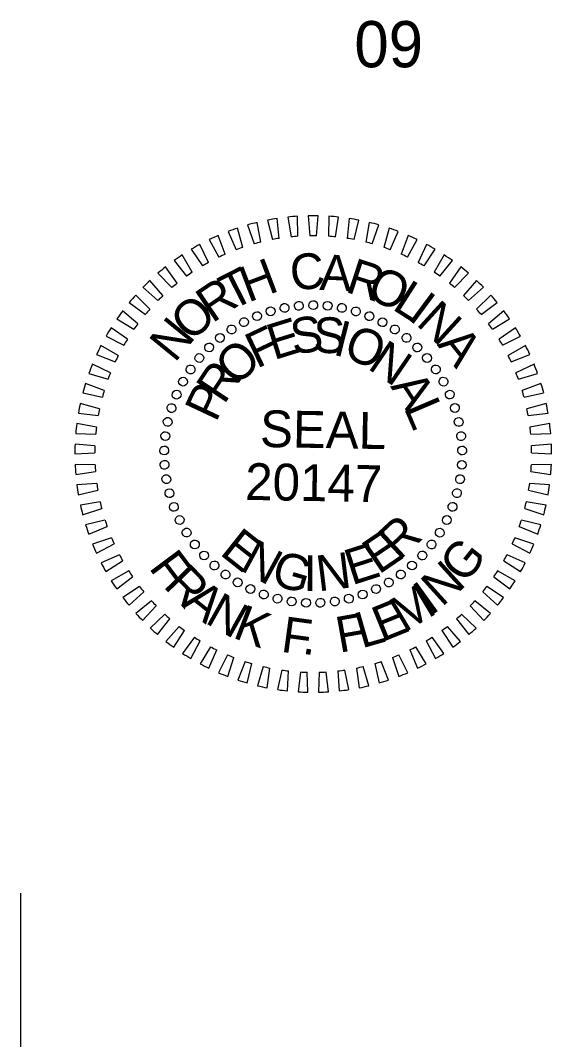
# Model space of a CAD drawing. Extents: x 2044664 to 2046614, y 755540 to 756566.
# Drawn here: x 2046401.6 to 2046490.8, y 756394.8 to 756565.9 of the extents above; entities that cross this region are included whole.
import ezdxf

# ---------------------------------------------------------------- set-up
doc = ezdxf.new("R2010")
doc.units = 0
for name, color, linetype in [('Matchline', 7, 'Continuous'), ('Sheet Data Field CELL', 7, 'Continuous'), ('Sheet PE Seal Cell', 7, 'Continuous')]:
    doc.layers.add(name, color=color, linetype=linetype)

msp = doc.modelspace()

# ---------------------------------------------------------------- linework, layer by layer
at = {"layer": 'Matchline'}
msp.add_line((2046401.63, 756419.36), (2046401.63, 756155.41), dxfattribs=at)
at = {"layer": 'Sheet PE Seal Cell'}
for p, q in [((2046443.1, 756532.35), (2046443.92, 756529.09)), ((2046445.05, 756529.29), (2046444.73, 756532.63)), ((2046446.51, 756532.86), (2046447.04, 756529.55)), ((2046448.19, 756529.65), (2046448.15, 756533)), ((2046449.94, 756533.08), (2046450.19, 756529.73)), ((2046451.34, 756529.73), (2046451.59, 756533.08)), ((2046453.38, 756533), (2046453.34, 756529.65)), ((2046454.49, 756529.55), (2046455.02, 756532.86)), ((2046456.8, 756532.63), (2046456.48, 756529.29)), ((2046457.61, 756529.09), (2046458.43, 756532.35)), ((2046436.49, 756530.45), (2046437.86, 756527.39)), ((2046438.94, 756527.78), (2046438.04, 756531.01)), ((2046439.76, 756531.54), (2046440.85, 756528.37)), ((2046441.96, 756528.67), (2046441.35, 756531.96)), ((2046460.18, 756531.96), (2046459.57, 756528.67)), ((2046460.68, 756528.37), (2046461.77, 756531.54)), ((2046463.49, 756531.01), (2046462.59, 756527.78)), ((2046463.68, 756527.39), (2046465.04, 756530.45)), ((2046433.33, 756529.09), (2046434.95, 756526.15)), ((2046436, 756526.63), (2046434.83, 756529.78)), ((2046466.7, 756529.78), (2046465.53, 756526.63)), ((2046466.58, 756526.15), (2046468.2, 756529.09)), ((2046430.3, 756527.46), (2046432.17, 756524.67)), ((2046433.17, 756525.24), (2046431.74, 756528.27)), ((2046469.79, 756528.27), (2046468.36, 756525.24)), ((2046469.36, 756524.67), (2046471.23, 756527.46)), ((2046427.42, 756525.57), (2046429.52, 756522.96)), ((2046430.47, 756523.61), (2046428.78, 756526.51)), ((2046472.75, 756526.51), (2046471.06, 756523.61)), ((2046472.01, 756522.96), (2046474.11, 756525.57)), ((2046427.92, 756521.75), (2046425.99, 756524.49)), ((2046475.54, 756524.49), (2046473.61, 756521.75)), ((2046425.54, 756519.68), (2046423.38, 756522.25)), ((2046424.72, 756523.44), (2046427.04, 756521.02)), ((2046474.49, 756521.02), (2046476.81, 756523.44)), ((2046478.15, 756522.25), (2046475.99, 756519.68)), ((2046422.2, 756521.09), (2046424.72, 756518.88)), ((2046476.81, 756518.88), (2046479.33, 756521.09)), ((2046419.9, 756518.53), (2046422.6, 756516.54)), ((2046423.35, 756517.41), (2046420.98, 756519.78)), ((2046480.55, 756519.78), (2046478.18, 756517.41)), ((2046478.93, 756516.54), (2046481.63, 756518.53)), ((2046421.36, 756514.97), (2046418.79, 756517.12)), ((2046482.74, 756517.12), (2046480.17, 756514.97)), ((2046417.83, 756515.79), (2046420.69, 756514.03)), ((2046480.84, 756514.03), (2046483.7, 756515.79)), ((2046419.59, 756512.36), (2046416.84, 756514.29)), ((2046484.69, 756514.29), (2046481.94, 756512.36)), ((2046416, 756512.87), (2046419, 756511.37)), ((2046482.53, 756511.37), (2046485.53, 756512.87)), ((2046414.43, 756509.81), (2046417.55, 756508.57)), ((2046418.05, 756509.61), (2046415.15, 756511.29)), ((2046486.38, 756511.29), (2046483.48, 756509.61)), ((2046483.98, 756508.57), (2046487.1, 756509.81)), ((2046416.75, 756506.73), (2046413.71, 756508.16)), ((2046487.82, 756508.16), (2046484.78, 756506.73)), ((2046413.12, 756506.62), (2046416.34, 756505.66)), ((2046485.19, 756505.66), (2046488.41, 756506.62)), ((2046415.7, 756503.76), (2046412.56, 756504.92)), ((2046488.97, 756504.92), (2046485.83, 756503.76)), ((2046412.1, 756503.34), (2046415.39, 756502.65)), ((2046486.14, 756502.65), (2046489.43, 756503.34)), ((2046414.92, 756500.7), (2046411.68, 756501.59)), ((2046489.85, 756501.59), (2046486.61, 756500.7)), ((2046411.36, 756499.97), (2046414.69, 756499.58)), ((2046486.84, 756499.58), (2046490.17, 756499.97)), ((2046414.39, 756497.59), (2046411.09, 756498.2)), ((2046490.44, 756498.2), (2046487.14, 756497.59)), ((2046410.92, 756496.56), (2046414.27, 756496.45)), ((2046487.26, 756496.45), (2046490.61, 756496.56)), ((2046414.14, 756494.45), (2046410.8, 756494.77)), ((2046490.73, 756494.77), (2046487.39, 756494.45)), ((2046410.77, 756493.12), (2046414.12, 756493.3)), ((2046450.77, 756493.09), (2046450.77, 756493.09)), ((2046487.41, 756493.3), (2046490.77, 756493.12)), ((2046414.16, 756491.3), (2046410.8, 756491.33)), ((2046490.73, 756491.33), (2046487.37, 756491.3)), ((2046410.91, 756489.68), (2046414.23, 756490.15)), ((2046487.3, 756490.15), (2046490.62, 756489.68)), ((2046414.45, 756488.16), (2046411.1, 756487.9)), ((2046490.43, 756487.9), (2046487.08, 756488.16)), ((2046411.35, 756486.27), (2046414.62, 756487.02)), ((2046486.91, 756487.02), (2046490.18, 756486.27)), ((2046415.01, 756485.05), (2046411.7, 756484.51)), ((2046489.83, 756484.51), (2046486.52, 756485.05)), ((2046412.08, 756482.91), (2046415.28, 756483.94)), ((2046486.25, 756483.94), (2046489.45, 756482.91)), ((2046415.83, 756482.01), (2046412.58, 756481.19)), ((2046413.1, 756479.62), (2046416.19, 756480.92)), ((2046485.34, 756480.92), (2046488.43, 756479.62)), ((2046488.95, 756481.19), (2046485.7, 756482.01)), ((2046416.91, 756479.05), (2046413.74, 756477.95)), ((2046487.79, 756477.95), (2046484.62, 756479.05)), ((2046414.4, 756476.43), (2046417.37, 756477.99)), ((2046484.16, 756477.99), (2046487.13, 756476.43)), ((2046418.24, 756476.19), (2046415.18, 756474.82)), ((2046486.35, 756474.82), (2046483.29, 756476.19)), ((2046415.96, 756473.37), (2046418.79, 756475.18)), ((2046482.74, 756475.18), (2046485.57, 756473.37)), ((2046419.82, 756473.46), (2046416.88, 756471.83)), ((2046417.79, 756470.45), (2046420.45, 756472.49)), ((2046481.08, 756472.49), (2046483.74, 756470.45)), ((2046484.65, 756471.83), (2046481.71, 756473.46)), ((2046421.62, 756470.87), (2046418.84, 756468.99)), ((2046482.69, 756468.99), (2046479.91, 756470.87)), ((2046419.86, 756467.7), (2046422.33, 756469.96)), ((2046479.2, 756469.96), (2046481.67, 756467.7)), ((2046423.64, 756468.44), (2046421.02, 756466.34)), ((2046422.15, 756465.14), (2046424.42, 756467.61)), ((2046477.11, 756467.61), (2046479.38, 756465.14)), ((2046480.51, 756466.34), (2046477.89, 756468.44)), ((2046425.86, 756466.2), (2046423.43, 756463.88)), ((2046424.66, 756462.78), (2046426.71, 756465.44)), ((2046474.82, 756465.44), (2046476.87, 756462.78)), ((2046478.1, 756463.88), (2046475.67, 756466.2)), ((2046428.26, 756464.16), (2046426.05, 756461.64)), ((2046475.48, 756461.64), (2046473.27, 756464.16)), ((2046427.36, 756460.65), (2046429.18, 756463.47)), ((2046430.83, 756462.33), (2046428.84, 756459.63)), ((2046472.69, 756459.63), (2046470.7, 756462.33)), ((2046472.35, 756463.47), (2046474.17, 756460.65)), ((2046430.24, 756458.76), (2046431.8, 756461.72)), ((2046433.55, 756460.73), (2046431.8, 756457.87)), ((2046433.27, 756457.12), (2046434.57, 756460.21)), ((2046466.96, 756460.21), (2046468.26, 756457.12)), ((2046469.73, 756457.87), (2046467.98, 756460.73)), ((2046469.73, 756461.72), (2046471.29, 756458.76)), ((2046436.39, 756459.37), (2046434.9, 756456.37)), ((2046436.42, 756455.75), (2046437.46, 756458.94)), ((2046464.07, 756458.94), (2046465.11, 756455.75)), ((2046466.63, 756456.37), (2046465.14, 756459.37)), ((2046439.34, 756458.26), (2046438.11, 756455.14)), ((2046439.69, 756454.65), (2046440.44, 756457.92)), ((2046442.38, 756457.41), (2046441.42, 756454.19)), ((2046443.03, 756453.84), (2046443.5, 756457.16)), ((2046445.48, 756456.82), (2046444.8, 756453.54)), ((2046456.73, 756453.54), (2046456.05, 756456.82)), ((2046458.03, 756457.16), (2046458.5, 756453.84)), ((2046460.11, 756454.19), (2046459.15, 756457.41)), ((2046461.09, 756457.92), (2046461.84, 756454.65)), ((2046463.42, 756455.14), (2046462.19, 756458.26)), ((2046446.43, 756453.32), (2046446.62, 756456.67)), ((2046448.61, 756456.5), (2046448.22, 756453.17)), ((2046449.87, 756453.1), (2046449.76, 756456.45)), ((2046451.77, 756456.45), (2046451.66, 756453.1)), ((2046453.31, 756453.17), (2046452.92, 756456.5)), ((2046454.91, 756456.67), (2046455.1, 756453.32))]:
    msp.add_line(p, q, dxfattribs=at)
for radius, start, end in [(40, 98.6812, 101.0448), (40, 93.7497, 96.1133), (40, 88.8182, 91.1818), (40, 83.8867, 86.2503), (40, 78.9552, 81.3188), (40, 108.5442, 110.9078), (40, 103.6127, 105.9763), (40, 74.0237, 76.3873), (40, 69.0922, 71.4558), (40, 113.4757, 115.8393), (36.65, 103.8956, 105.6935), (36.65, 98.9641, 100.762), (36.65, 94.0326, 95.8305), (36.65, 89.1011, 90.8989), (36.65, 84.1695, 85.9674), (36.65, 79.238, 81.0359), (36.65, 74.3065, 76.1044), (40, 64.1607, 66.5243), (40, 118.4072, 120.7709), (36.65, 108.8271, 110.625), (36.65, 69.375, 71.1729), (40, 59.2291, 61.5928), (40, 123.3387, 125.7024), (36.65, 118.6901, 120.488), (36.65, 113.7586, 115.5565), (36.65, 64.4435, 66.2414), (36.65, 59.512, 61.3099), (40, 54.2976, 56.6613), (40, 128.2702, 130.6339), (36.65, 123.6216, 125.4195), (36.65, 54.5805, 56.3784), (40, 49.3661, 51.7298), (40, 133.2018, 135.5654), (40, 44.4346, 46.7982), (36.65, 128.5531, 130.351), (36.65, 49.649, 51.4469), (40, 138.1333, 140.4969), (36.65, 133.4846, 135.2825), (36.65, 44.7175, 46.5154), (40, 39.5031, 41.8667), (40, 143.0648, 145.4284), (36.65, 138.4161, 140.214), (36.65, 39.786, 41.5839), (40, 34.5716, 36.9352), (36.65, 143.3476, 145.1455), (36.65, 34.8545, 36.6524), (40, 147.9963, 150.3599), (40, 29.6401, 32.0037), (36.65, 148.2791, 150.077), (36.65, 29.923, 31.7209), (40, 152.9278, 155.2914), (40, 24.7086, 27.0722), (40, 157.8593, 160.2229), (36.65, 153.2106, 155.0085), (36.65, 24.9915, 26.7894), (40, 19.7771, 22.1407), (36.65, 158.1421, 159.94), (36.65, 20.06, 21.8579), (40, 162.7908, 165.1544), (40, 14.8456, 17.2092), (36.65, 163.0737, 164.8716), (36.65, 15.1284, 16.9263), (40, 167.7223, 170.0859), (40, 9.9141, 12.2777), (36.65, 168.0052, 169.8031), (36.65, 10.1969, 11.9948), (40, 172.6538, 175.0174), (40, 4.9826, 7.3462), (36.65, 172.9367, 174.7346), (36.65, 5.2654, 7.0633), (40, 177.5853, 179.9489), (36.65, 177.8682, 179.6661), (36.65, 0.3339, 2.1318), (40, 0.0511, 2.4147), (40, 182.5168, 184.8804), (36.65, 182.7997, 184.5976), (36.65, 355.4024, 357.2003), (40, 355.1196, 357.4832), (40, 187.4483, 189.8119), (36.65, 187.7312, 189.5291), (36.65, 350.4709, 352.2688), (40, 350.1881, 352.5517), (40, 192.3798, 194.7435), (36.65, 192.6627, 194.4606), (36.65, 345.5394, 347.3373), (40, 345.2565, 347.6202), (40, 197.3113, 199.675), (36.65, 197.5942, 199.3921), (36.65, 340.6079, 342.4058), (40, 340.325, 342.6887), (36.65, 202.5257, 204.3236), (36.65, 335.6764, 337.4743), (40, 202.2428, 204.6065), (40, 335.3935, 337.7572), (36.65, 207.4572, 209.2551), (36.65, 330.7449, 332.5428), (40, 207.1744, 209.538), (40, 330.462, 332.8256), (36.65, 212.3887, 214.1866), (36.65, 325.8134, 327.6113), (40, 212.1059, 214.4695), (36.65, 217.3202, 219.1181), (36.65, 320.8819, 322.6798), (40, 325.5305, 327.8941), (40, 217.0374, 219.401), (40, 320.599, 322.9626), (36.65, 222.2517, 224.0496), (36.65, 315.9504, 317.7483), (40, 221.9689, 224.3325), (36.65, 227.1832, 228.9811), (36.65, 311.0189, 312.8168), (40, 315.6675, 318.0311), (40, 226.9004, 229.264), (36.65, 232.1148, 233.9126), (36.65, 306.0874, 307.8852), (40, 310.736, 313.0996), (36.65, 237.0463, 238.8442), (36.65, 301.1558, 302.9537), (40, 231.8319, 234.1955), (36.65, 241.9778, 243.7757), (36.65, 296.2243, 298.0222), (40, 305.8045, 308.1681), (40, 236.7634, 239.127), (36.65, 246.9093, 248.7072), (36.65, 291.2928, 293.0907), (40, 300.873, 303.2366), (40, 241.6949, 244.0585), (36.65, 251.8408, 253.6387), (36.65, 256.7723, 258.5702), (36.65, 261.7038, 263.5017), (36.65, 276.4983, 278.2962), (36.65, 281.4298, 283.2277), (36.65, 286.3613, 288.1592), (40, 295.9415, 298.3051), (40, 246.6264, 248.99), (40, 251.5579, 253.9215), (36.65, 266.6353, 268.4332), (36.65, 271.5668, 273.3647), (40, 286.0785, 288.4421), (40, 291.01, 293.3736), (40, 256.4894, 258.853), (40, 261.4209, 263.7845), (40, 276.2155, 278.5791), (40, 281.147, 283.5106), (40, 266.3524, 268.7161), (40, 271.2839, 273.6476)]:
    msp.add_arc((2046450.77, 756493.09), radius, start, end, dxfattribs=at)
for centre, major_axis in [((2046445.96, 756517.62), (-0.193, 0.717)), ((2046448.35, 756517.97), (-0.123, 0.732)), ((2046450.77, 756518.09), (-0.052, 0.741)), ((2046453.18, 756517.97), (0.02, 0.742)), ((2046455.57, 756517.62), (0.091, 0.737)), ((2046441.34, 756516.24), (-0.327, 0.666)), ((2046443.62, 756517.04), (-0.261, 0.695)), ((2046457.91, 756517.04), (0.162, 0.724)), ((2046460.19, 756516.24), (0.231, 0.705)), ((2046439.15, 756515.22), (-0.39, 0.632)), ((2046462.38, 756515.22), (0.298, 0.68)), ((2046435.11, 756512.58), (-0.504, 0.545)), ((2046437.06, 756514), (-0.449, 0.591)), ((2046464.47, 756514), (0.363, 0.648)), ((2046466.42, 756512.58), (0.423, 0.61)), ((2046433.3, 756510.98), (-0.554, 0.494)), ((2046468.23, 756510.98), (0.48, 0.566)), ((2046431.66, 756509.21), (-0.599, 0.438)), ((2046469.87, 756509.21), (0.533, 0.517)), ((2046430.19, 756507.29), (-0.639, 0.378)), ((2046471.34, 756507.29), (0.58, 0.463)), ((2046428.92, 756505.24), (-0.672, 0.315)), ((2046472.61, 756505.24), (0.622, 0.405)), ((2046427.85, 756503.07), (-0.7, 0.248)), ((2046473.68, 756503.07), (0.658, 0.343)), ((2046426.99, 756500.81), (-0.72, 0.18)), ((2046474.54, 756500.81), (0.688, 0.278)), ((2046426.35, 756498.48), (-0.734, 0.109)), ((2046475.18, 756498.48), (0.712, 0.21)), ((2046425.95, 756496.1), (-0.741, 0.038)), ((2046475.58, 756496.1), (0.729, 0.141)), ((2046425.77, 756493.69), (-0.742, -0.034)), ((2046475.76, 756493.69), (0.739, 0.07)), ((2046425.83, 756491.28), (-0.735, -0.105)), ((2046475.7, 756491.28), (0.742, -0.002)), ((2046426.12, 756488.88), (-0.721, -0.176)), ((2046475.41, 756488.88), (0.739, -0.074)), ((2046426.64, 756486.52), (-0.701, -0.245)), ((2046474.89, 756486.52), (0.728, -0.145)), ((2046427.39, 756484.22), (-0.674, -0.311)), ((2046474.14, 756484.22), (0.711, -0.214)), ((2046428.35, 756482.01), (-0.641, -0.375)), ((2046473.18, 756482.01), (0.687, -0.282)), ((2046429.53, 756479.9), (-0.602, -0.435)), ((2046472, 756479.9), (0.656, -0.347)), ((2046430.9, 756477.91), (-0.557, -0.491)), ((2046470.63, 756477.91), (0.62, -0.408)), ((2046432.46, 756476.06), (-0.507, -0.542)), ((2046469.07, 756476.06), (0.578, -0.466)), ((2046434.19, 756474.38), (-0.452, -0.589)), ((2046467.34, 756474.38), (0.53, -0.52)), ((2046436.07, 756472.86), (-0.393, -0.63)), ((2046438.09, 756471.54), (-0.331, -0.665)), ((2046463.44, 756471.54), (0.42, -0.612)), ((2046465.46, 756472.86), (0.477, -0.569)), ((2046440.23, 756470.42), (-0.265, -0.693)), ((2046461.3, 756470.42), (0.359, -0.65)), ((2046442.47, 756469.51), (-0.197, -0.716)), ((2046444.78, 756468.81), (-0.127, -0.731)), ((2046447.15, 756468.35), (-0.056, -0.74)), ((2046449.56, 756468.12), (0.016, -0.742)), ((2046451.97, 756468.12), (0.087, -0.737)), ((2046454.38, 756468.35), (0.158, -0.725)), ((2046456.75, 756468.81), (0.227, -0.707)), ((2046459.06, 756469.51), (0.295, -0.681))]:
    msp.add_ellipse(centre, major_axis=major_axis, ratio=0.999708, dxfattribs=at)

# ---------------------------------------------------------------- texts
at = {"layer": 'Sheet Data Field CELL'}
msp.add_text('09', height=7.75, dxfattribs=at).set_placement((2046457.67, 756558.02))
at = {"layer": 'Sheet PE Seal Cell'}
for s, height, rotation, p in [('C', 6, 6.2923, (2046447.2, 756520.46)), ('H', 6, 20.6611, (2046439.85, 756518.49)), ('A', 6, 357.4079, (2046451.76, 756520.65)), ('R', 6, 341.9207, (2046455.98, 756520.37)), ('T', 6, 27.0543, (2046437.07, 756517.11)), ('O', 6, 334.6314, (2046459.44, 756519.51)), ('R', 6, 34.1512, (2046433.82, 756514.97)), ('L', 6, 327.4311, (2046463.84, 756517.49)), ('I', 6, 323.4435, (2046466.43, 756515.85)), ('O', 6, 41.8138, (2046430.22, 756511.76)), ('N', 6, 317.607, (2046467.87, 756514.87)), ('N', 6, 50.8336, (2046427.53, 756508.28)), ('E', 6, 17.1847, (2046444.15, 756508.83)), ('S', 6, 8.3855, (2046447.41, 756509.77)), ('S', 6, 0.0054, (2046450.81, 756510.04)), ('I', 6, 345.8454, (2046453.89, 756509.82)), ('F', 6, 25.4119, (2046441.3, 756507.37)), ('O', 6, 337.4556, (2046455.55, 756509.51)), ('A', 6, 308.6767, (2046471.46, 756511.43)), ('O', 6, 44.3595, (2046437.93, 756504.29)), ('N', 6, 325.7421, (2046459.71, 756507.53)), ('R', 6, 56.2858, (2046435.79, 756501.27)), ('P', 6, 64.7931, (2046434.44, 756498.27)), ('A', 6, 303.2217, (2046463.64, 756504.44)), ('L', 6, 293.0887, (2046465.93, 756500.87)), ('SEAL', 6.184, 359, (2046441.8, 756494.28)), ('20147', 6.185, 359, (2046439.31, 756485.4)), ('R', 6, 42.9977, (2046465.17, 756475.07)), ('E', 6, 321.5743, (2046434.91, 756476.33)), ('E', 6, 34.2447, (2046461.76, 756472.78)), ('N', 6, 331.4279, (2046438.24, 756473.72)), ('E', 6, 17.841, (2046457.25, 756471.02)), ('G', 6, 51.4479, (2046476.23, 756471.11)), ('F', 6, 306.7615, (2046423.06, 756474)), ('G', 6, 343.9576, (2046443.46, 756471.28)), ('I', 6, 359.5423, (2046449.11, 756470.12)), ('N', 6, 6.9918, (2046451.63, 756470.02)), ('R', 6, 313.9689, (2046425.46, 756470.89)), ('N', 6, 42.1117, (2046472.34, 756467.29)), ('A', 6, 321.4168, (2046428.6, 756467.76)), ('M', 6, 30.81, (2046466.01, 756463.03)), ('I', 6, 35.7562, (2046470.46, 756465.85)), ('N', 6, 330.6566, (2046432.43, 756464.83)), ('E', 6, 22.1677, (2046462.27, 756461.47)), ('K', 6, 339.031, (2046437.08, 756462.33)), ('F', 6, 352.1941, (2046445.21, 756459.92)), ('F', 6, 10.0116, (2046455.15, 756459.72)), ('L', 6, 16.0513, (2046458.89, 756460.44)), ('.', 6, 350.5584, (2046448.79, 756459.62))]:
    msp.add_text(s, height=height, rotation=rotation, dxfattribs=at).set_placement(p)

doc.saveas('drawing.dxf')
